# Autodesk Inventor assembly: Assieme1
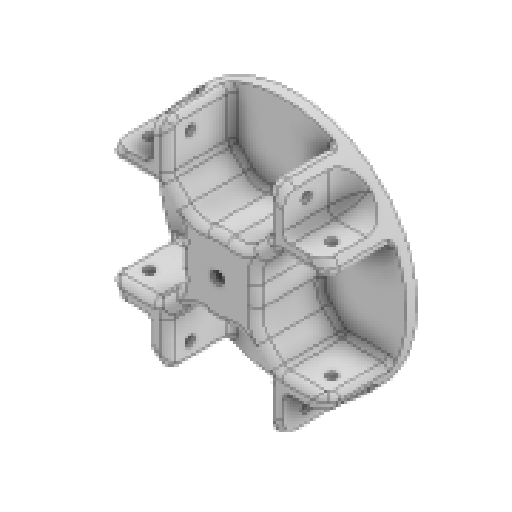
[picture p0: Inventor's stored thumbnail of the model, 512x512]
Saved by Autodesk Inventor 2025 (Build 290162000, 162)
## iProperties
Created: 2025-05
Part Number: Assieme1
Document SubType Name: Assembly
Designer: R5800u
Author: R5800u
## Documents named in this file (2)
- C:\Users\R5800u\Desktop\mecanum4\Assieme1.iam
- C:\Users\R5800u\Desktop\mecanum4\Parte1b.ipt
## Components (1 placed, 1 different names)
1. Parte1b:1
